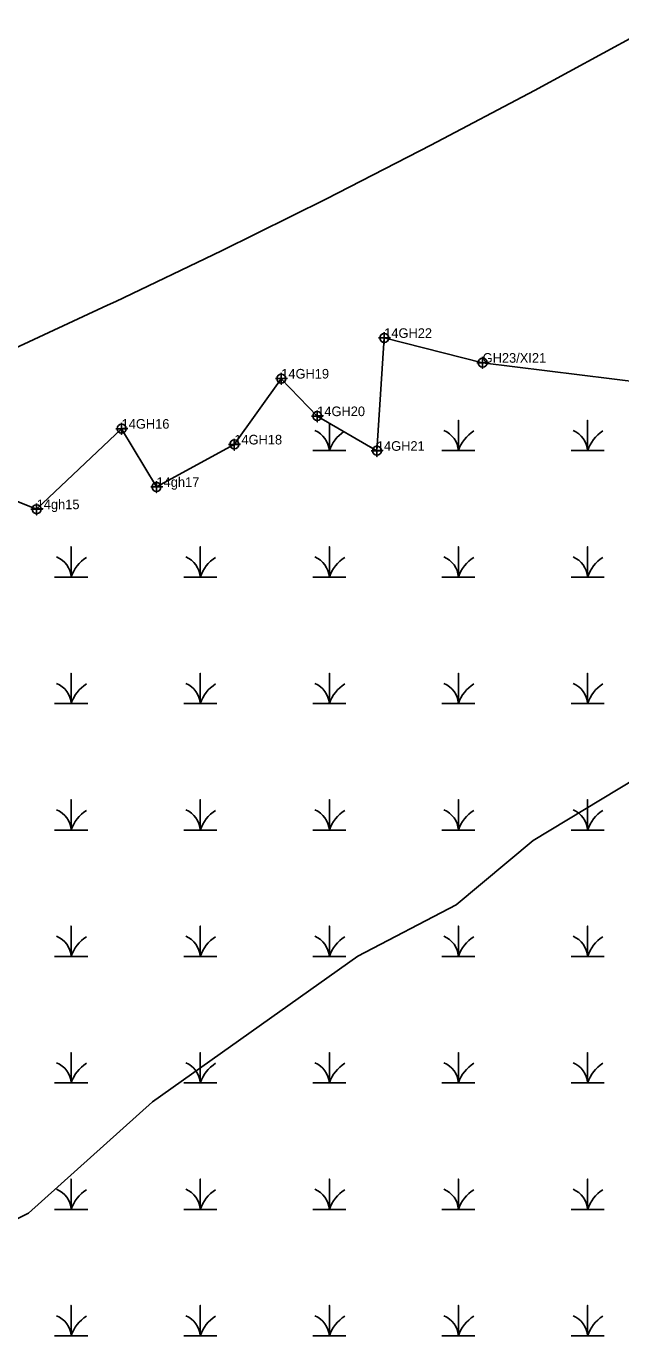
# Model space of a CAD drawing. Extents: x 2071991 to 2268989, y 436479 to 469629.
# Drawn here: x 2263986 to 2264295, y 442665 to 443346 of the extents above; entities that cross this region are included whole.
import ezdxf

# ---------------------------------------------------------------- set-up
doc = ezdxf.new("R2010")
doc.units = 0
for name, color, linetype in [('approx_PSA', 7, 'Continuous'), ('Exist Environmental Wetland Boundary', 7, 'Continuous'), ('Exist Environmental Wetland Boundary Cogo Comment', 7, 'Continuous'), ('Exist Environmental Wetland Boundary Cogo Point CELL', 7, 'Continuous'), ('Exist Hydro Jurisdictional Stream or Body of Water NEU Mitigable', 7, 'Continuous'), ('Exist Hydro Swamp or Marsh', 7, 'Continuous')]:
    doc.layers.add(name, color=color, linetype=linetype)

msp = doc.modelspace()

# ---------------------------------------------------------------- linework, layer by layer
at = {"layer": 'approx_PSA'}
for p, q in [((2264250.37, 443312.35), (2264303.97, 443341.53)), ((2264196.39, 443283.86), (2264250.37, 443312.35)), ((2264142.05, 443256.07), (2264196.39, 443283.86)), ((2264087.36, 443228.98), (2264142.05, 443256.07)), ((2264032.32, 443202.6), (2264087.36, 443228.98)), ((2263976.94, 443176.93), (2264028.06, 443200.63)), ((2264028.06, 443200.63), (2264032.32, 443202.6))]:
    msp.add_line(p, q, dxfattribs=at)
at = {"layer": 'Exist Environmental Wetland Boundary'}
for points in [[(2264223.31, 443170.74), (2264357.83, 443154.1), (2264403.79, 443177.74), (2264439.35, 443212.19), (2264430.87, 443248.17), (2264398.35, 443264.38), (2264370.42, 443270.46), (2264357.87, 443292.26), (2264333.71, 443322.37), (2264312.34, 443343.4), (2264311.59, 443345.81)], [(2263685.65, 442855.81), (2263685.86, 442913.44), (2263681.01, 442959.68), (2263666.2, 442975.24), (2263717.57, 442990.36), (2263736.22, 443017.59), (2263772.08, 443011.89), (2263791.56, 442959.23), (2263814.96, 442950.75), (2263833.34, 442988.29), (2263882.26, 443012.92), (2263904.25, 443055.08), (2263915.31, 443091.9), (2263946.68, 443112.43), (2263991.16, 443094.56), (2264035.37, 443136.43), (2264053.54, 443106.16), (2264094.03, 443128.23), (2264118.46, 443162.37), (2264137.19, 443142.96), (2264168.26, 443124.93), (2264172.08, 443183.66), (2264223.31, 443170.74)], [(2264164.85, 443126.91), (2264168.26, 443124.93), (2264168.43, 443127.59)], [(2264164.85, 443126.91), (2264168.26, 443124.93), (2264168.43, 443127.59)]]:
    msp.add_lwpolyline(points, dxfattribs=at)
at = {"layer": 'Exist Environmental Wetland Boundary Cogo Point CELL'}
for points in [[(2264172.08, 443186.66), (2264172.08, 443180.66), (2264172.08, 443183.66), (2264175.08, 443183.66), (2264169.08, 443183.66)], [(2264223.31, 443173.74), (2264223.31, 443167.74), (2264223.31, 443170.74), (2264226.31, 443170.74), (2264220.31, 443170.74)], [(2264118.47, 443165.51), (2264118.47, 443159.51), (2264118.47, 443162.51), (2264121.47, 443162.51), (2264115.47, 443162.51)], [(2264137.19, 443145.96), (2264137.19, 443139.96), (2264137.19, 443142.96), (2264140.19, 443142.96), (2264134.19, 443142.96)], [(2264035.37, 443139.43), (2264035.37, 443133.43), (2264035.37, 443136.43), (2264038.37, 443136.43), (2264032.37, 443136.43)], [(2264094.03, 443131.23), (2264094.03, 443125.23), (2264094.03, 443128.23), (2264097.03, 443128.23), (2264091.03, 443128.23)], [(2264168.26, 443127.93), (2264168.26, 443121.93), (2264168.26, 443124.93), (2264171.26, 443124.93), (2264165.26, 443124.93)], [(2264053.54, 443109.16), (2264053.54, 443103.16), (2264053.54, 443106.16), (2264056.54, 443106.16), (2264050.54, 443106.16)], [(2263991.16, 443097.56), (2263991.16, 443091.56), (2263991.16, 443094.56), (2263994.16, 443094.56), (2263988.16, 443094.56)]]:
    msp.add_lwpolyline(points, dxfattribs=at)
for centre in [(2264172.08, 443183.66), (2264223.31, 443170.74), (2264118.47, 443162.51), (2264137.19, 443142.96), (2264035.37, 443136.43), (2264094.03, 443128.23), (2264168.26, 443124.93), (2264053.54, 443106.16), (2263991.16, 443094.56)]:
    msp.add_circle(centre, 2.34, dxfattribs=at)
at = {"layer": 'Exist Hydro Jurisdictional Stream or Body of Water NEU Mitigable'}
msp.add_lwpolyline([(2264498.91, 443198.38), (2264443.26, 443120.42), (2264356.45, 442986.77), (2264249.6, 442922.17), (2264209.53, 442888.76), (2264158.34, 442862.03), (2264051.49, 442786.29), (2263986.94, 442728.38), (2263946.87, 442708.33)], dxfattribs=at)
at = {"layer": 'Exist Hydro Swamp or Marsh'}
for points in [[(2264134.92, 443125.02), (2264143.52, 443125.02), (2264143.52, 443139.29)], [(2264143.52, 443139.29), (2264143.52, 443125.02), (2264152.13, 443125.02)], [(2264202.13, 443125.02), (2264210.73, 443125.02), (2264210.73, 443140.8), (2264210.73, 443125.02), (2264219.33, 443125.02)], [(2264269.33, 443125.02), (2264277.93, 443125.02), (2264277.93, 443140.8), (2264277.93, 443125.02), (2264286.53, 443125.02)], [(2264000.52, 443059.24), (2264009.12, 443059.24), (2264009.12, 443075.02), (2264009.12, 443059.24), (2264017.72, 443059.24)], [(2264067.72, 443059.24), (2264076.32, 443059.24), (2264076.32, 443075.02), (2264076.32, 443059.24), (2264084.92, 443059.24)], [(2264134.92, 443059.24), (2264143.52, 443059.24), (2264143.52, 443075.02), (2264143.52, 443059.24), (2264152.13, 443059.24)], [(2264202.13, 443059.24), (2264210.73, 443059.24), (2264210.73, 443075.02), (2264210.73, 443059.24), (2264219.33, 443059.24)], [(2264269.33, 443059.24), (2264277.93, 443059.24), (2264277.93, 443075.02), (2264277.93, 443059.24), (2264286.53, 443059.24)], [(2264000.52, 442993.46), (2264009.12, 442993.46), (2264009.12, 443009.24), (2264009.12, 442993.46), (2264017.72, 442993.46)], [(2264067.72, 442993.46), (2264076.32, 442993.46), (2264076.32, 443009.24), (2264076.32, 442993.46), (2264084.92, 442993.46)], [(2264134.92, 442993.46), (2264143.52, 442993.46), (2264143.52, 443009.24), (2264143.52, 442993.46), (2264152.13, 442993.46)], [(2264202.13, 442993.46), (2264210.73, 442993.46), (2264210.73, 443009.24), (2264210.73, 442993.46), (2264219.33, 442993.46)], [(2264269.33, 442993.46), (2264277.93, 442993.46), (2264277.93, 443009.24), (2264277.93, 442993.46), (2264286.53, 442993.46)], [(2264000.52, 442927.67), (2264009.12, 442927.67), (2264009.12, 442943.46), (2264009.12, 442927.67), (2264017.72, 442927.67)], [(2264067.72, 442927.67), (2264076.32, 442927.67), (2264076.32, 442943.46), (2264076.32, 442927.67), (2264084.92, 442927.67)], [(2264134.92, 442927.67), (2264143.52, 442927.67), (2264143.52, 442943.46), (2264143.52, 442927.67), (2264152.13, 442927.67)], [(2264202.13, 442927.67), (2264210.73, 442927.67), (2264210.73, 442943.46), (2264210.73, 442927.67), (2264219.33, 442927.67)], [(2264269.33, 442927.67), (2264277.93, 442927.67), (2264277.93, 442943.46), (2264277.93, 442927.67), (2264286.53, 442927.67)], [(2264000.52, 442861.89), (2264009.12, 442861.89), (2264009.12, 442877.67), (2264009.12, 442861.89), (2264017.72, 442861.89)], [(2264067.72, 442861.89), (2264076.32, 442861.89), (2264076.32, 442877.67), (2264076.32, 442861.89), (2264084.92, 442861.89)], [(2264134.92, 442861.89), (2264143.52, 442861.89), (2264143.52, 442877.67), (2264143.52, 442861.89), (2264152.13, 442861.89)], [(2264202.13, 442861.89), (2264210.73, 442861.89), (2264210.73, 442877.67), (2264210.73, 442861.89), (2264219.33, 442861.89)], [(2264269.33, 442861.89), (2264277.93, 442861.89), (2264277.93, 442877.67), (2264277.93, 442861.89), (2264286.53, 442861.89)], [(2264000.52, 442796.11), (2264009.12, 442796.11), (2264009.12, 442811.89), (2264009.12, 442796.11), (2264017.72, 442796.11)], [(2264067.72, 442796.11), (2264076.32, 442796.11), (2264076.32, 442811.89), (2264076.32, 442796.11), (2264084.92, 442796.11)], [(2264134.92, 442796.11), (2264143.52, 442796.11), (2264143.52, 442811.89), (2264143.52, 442796.11), (2264152.13, 442796.11)], [(2264202.13, 442796.11), (2264210.73, 442796.11), (2264210.73, 442811.89), (2264210.73, 442796.11), (2264219.33, 442796.11)], [(2264269.33, 442796.11), (2264277.93, 442796.11), (2264277.93, 442811.89), (2264277.93, 442796.11), (2264286.53, 442796.11)], [(2264000.52, 442730.33), (2264009.12, 442730.33), (2264009.12, 442746.11), (2264009.12, 442730.33), (2264017.72, 442730.33)], [(2264067.72, 442730.33), (2264076.32, 442730.33), (2264076.32, 442746.11), (2264076.32, 442730.33), (2264084.92, 442730.33)], [(2264134.92, 442730.33), (2264143.52, 442730.33), (2264143.52, 442746.11), (2264143.52, 442730.33), (2264152.13, 442730.33)], [(2264202.13, 442730.33), (2264210.73, 442730.33), (2264210.73, 442746.11), (2264210.73, 442730.33), (2264219.33, 442730.33)], [(2264269.33, 442730.33), (2264277.93, 442730.33), (2264277.93, 442746.11), (2264277.93, 442730.33), (2264286.53, 442730.33)], [(2264000.52, 442664.55), (2264009.12, 442664.55), (2264009.12, 442680.33), (2264009.12, 442664.55), (2264017.72, 442664.55)], [(2264067.72, 442664.55), (2264076.32, 442664.55), (2264076.32, 442680.33), (2264076.32, 442664.55), (2264084.92, 442664.55)], [(2264134.92, 442664.55), (2264143.52, 442664.55), (2264143.52, 442680.33), (2264143.52, 442664.55), (2264152.13, 442664.55)], [(2264202.13, 442664.55), (2264210.73, 442664.55), (2264210.73, 442680.33), (2264210.73, 442664.55), (2264219.33, 442664.55)], [(2264269.33, 442664.55), (2264277.93, 442664.55), (2264277.93, 442680.33), (2264277.93, 442664.55), (2264286.53, 442664.55)]]:
    msp.add_lwpolyline(points, dxfattribs=at)
for centre, radius, start, end in [((2264131.26, 443124.13), 12.3, 4.14034, 67.53497), ((2264161.77, 443118.96), 19.22, 123.86782, 161.62219), ((2264198.46, 443124.13), 12.3, 4.14034, 67.53497), ((2264228.97, 443118.96), 19.22, 122.12745, 161.62219), ((2264265.66, 443124.13), 12.3, 4.14034, 67.53497), ((2264296.17, 443118.96), 19.22, 122.12745, 161.62219), ((2263996.85, 443058.35), 12.3, 4.14034, 67.53497), ((2264027.36, 443053.18), 19.22, 122.12745, 161.62219), ((2264064.05, 443058.35), 12.3, 4.14034, 67.53497), ((2264094.56, 443053.18), 19.22, 122.12745, 161.62219), ((2264131.26, 443058.35), 12.3, 4.14034, 67.53497), ((2264161.77, 443053.18), 19.22, 122.12745, 161.62219), ((2264198.46, 443058.35), 12.3, 4.14034, 67.53497), ((2264228.97, 443053.18), 19.22, 122.12745, 161.62219), ((2264265.66, 443058.35), 12.3, 4.14034, 67.53497), ((2264296.17, 443053.18), 19.22, 122.12745, 161.62219), ((2263996.85, 442992.57), 12.3, 4.14034, 67.53497), ((2264027.36, 442987.39), 19.22, 122.12745, 161.62219), ((2264064.05, 442992.57), 12.3, 4.14034, 67.53497), ((2264094.56, 442987.39), 19.22, 122.12745, 161.62219), ((2264131.26, 442992.57), 12.3, 4.14034, 67.53497), ((2264161.77, 442987.39), 19.22, 122.12745, 161.62219), ((2264198.46, 442992.57), 12.3, 4.14034, 67.53497), ((2264228.97, 442987.39), 19.22, 122.12745, 161.62219), ((2264265.66, 442992.57), 12.3, 4.14034, 67.53497), ((2264296.17, 442987.39), 19.22, 122.12745, 161.62219), ((2263996.85, 442926.79), 12.3, 4.14034, 67.53497), ((2264027.36, 442921.61), 19.22, 122.12745, 161.62219), ((2264064.05, 442926.79), 12.3, 4.14034, 67.53497), ((2264094.56, 442921.61), 19.22, 122.12745, 161.62219), ((2264131.26, 442926.79), 12.3, 4.14034, 67.53497), ((2264161.77, 442921.61), 19.22, 122.12745, 161.62219), ((2264198.46, 442926.79), 12.3, 4.14034, 67.53497), ((2264228.97, 442921.61), 19.22, 122.12745, 161.62219), ((2264265.66, 442926.79), 12.3, 4.14034, 67.53497), ((2264296.17, 442921.61), 19.22, 122.12745, 161.62219), ((2263996.85, 442861.01), 12.3, 4.14034, 67.53497), ((2264027.36, 442855.83), 19.22, 122.12745, 161.62219), ((2264064.05, 442861.01), 12.3, 4.14034, 67.53497), ((2264094.56, 442855.83), 19.22, 122.12745, 161.62219), ((2264131.26, 442861.01), 12.3, 4.14034, 67.53497), ((2264161.77, 442855.83), 19.22, 122.12745, 161.62219), ((2264198.46, 442861.01), 12.3, 4.14034, 67.53497), ((2264228.97, 442855.83), 19.22, 122.12745, 161.62219), ((2264265.66, 442861.01), 12.3, 4.14034, 67.53497), ((2264296.17, 442855.83), 19.22, 122.12745, 161.62219), ((2263996.85, 442795.23), 12.3, 4.14034, 67.53497), ((2264027.36, 442790.05), 19.22, 122.12745, 161.62219), ((2264064.05, 442795.23), 12.3, 4.14034, 67.53497), ((2264094.56, 442790.05), 19.22, 122.12745, 161.62219), ((2264131.26, 442795.23), 12.3, 4.14034, 67.53497), ((2264161.77, 442790.05), 19.22, 122.12745, 161.62219), ((2264198.46, 442795.23), 12.3, 4.14034, 67.53497), ((2264228.97, 442790.05), 19.22, 122.12745, 161.62219), ((2264265.66, 442795.23), 12.3, 4.14034, 67.53497), ((2264296.17, 442790.05), 19.22, 122.12745, 161.62219), ((2263996.85, 442729.45), 12.3, 4.14034, 67.53497), ((2264027.36, 442724.27), 19.22, 122.12745, 161.62219), ((2264064.05, 442729.45), 12.3, 4.14034, 67.53497), ((2264094.56, 442724.27), 19.22, 122.12745, 161.62219), ((2264131.26, 442729.45), 12.3, 4.14034, 67.53497), ((2264161.77, 442724.27), 19.22, 122.12745, 161.62219), ((2264198.46, 442729.45), 12.3, 4.14034, 67.53497), ((2264228.97, 442724.27), 19.22, 122.12745, 161.62219), ((2264265.66, 442729.45), 12.3, 4.14034, 67.53497), ((2264296.17, 442724.27), 19.22, 122.12745, 161.62219), ((2263996.85, 442663.66), 12.3, 4.14034, 67.53497), ((2264027.36, 442658.49), 19.22, 122.12745, 161.62219), ((2264064.05, 442663.66), 12.3, 4.14034, 67.53497), ((2264094.56, 442658.49), 19.22, 122.12745, 161.62219), ((2264131.26, 442663.66), 12.3, 4.14034, 67.53497), ((2264161.77, 442658.49), 19.22, 122.12745, 161.62219), ((2264198.46, 442663.66), 12.3, 4.14034, 67.53497), ((2264228.97, 442658.49), 19.22, 122.12745, 161.62219), ((2264265.66, 442663.66), 12.3, 4.14034, 67.53497), ((2264296.17, 442658.49), 19.22, 122.12745, 161.62219)]:
    msp.add_arc(centre, radius, start, end, dxfattribs=at)

# ---------------------------------------------------------------- texts
at = {"layer": 'Exist Environmental Wetland Boundary Cogo Comment'}
for s, p in [('14GH22', (2264172.08, 443183.66)), ('GH23/XI21', (2264223.31, 443170.74)), ('14GH19', (2264118.47, 443162.51)), ('14GH20', (2264137.19, 443142.96)), ('14GH16', (2264035.37, 443136.43)), ('14GH18', (2264094.03, 443128.23)), ('14GH21', (2264168.26, 443124.93)), ('14gh17', (2264053.54, 443106.16)), ('14gh15', (2263991.16, 443094.56))]:
    msp.add_text(s, height=5, dxfattribs=at).set_placement(p)

doc.saveas('drawing.dxf')
